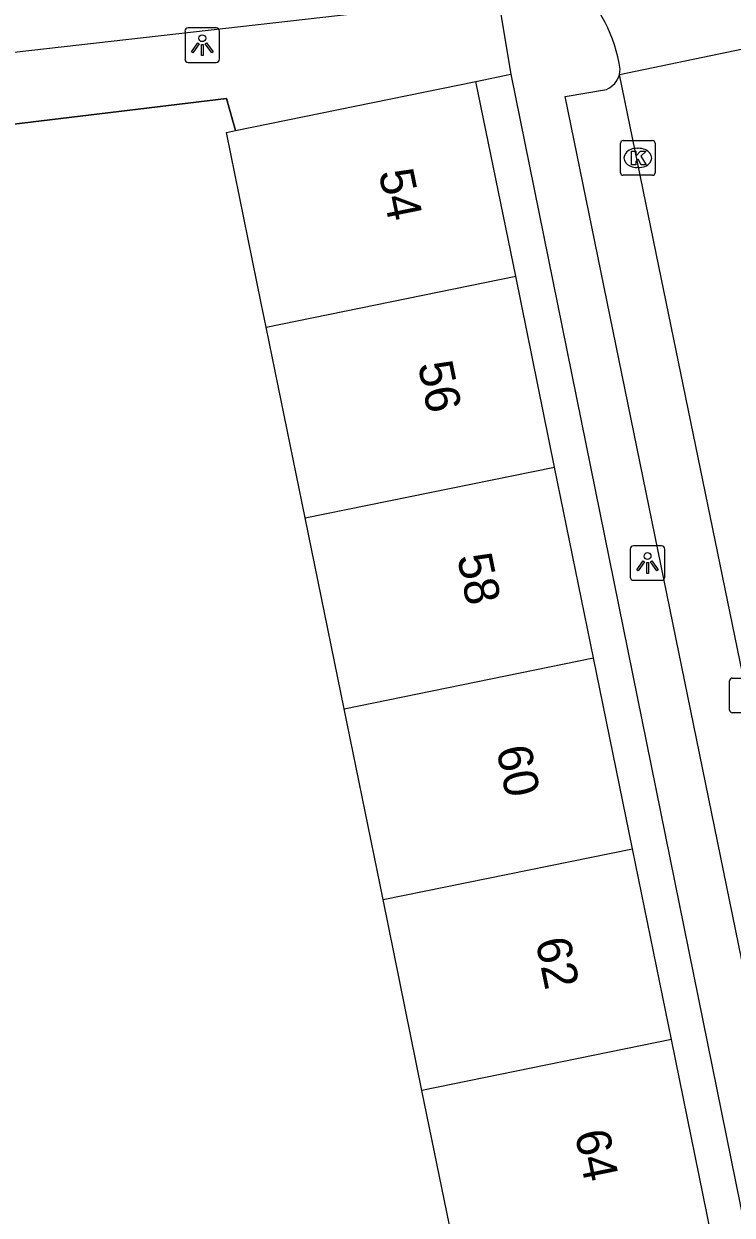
# Model space of a CAD drawing. Extents: x 162250 to 162654, y 380744 to 381605.
# Drawn here: x 162526.36 to 162546.81, y 380863.65 to 380898.07 of the extents above; entities that cross this region are included whole.
import ezdxf

# ---------------------------------------------------------------- set-up
doc = ezdxf.new("R2010")
doc.units = 0
for name, color, linetype in [('IMGEO_Kolk', 7, 'Continuous'), ('IMGEO_Lichtpunt', 7, 'Continuous'), ('IMGEO_Muur', 7, 'Continuous'), ('IMGEO_Pand', 7, 'Continuous'), ('IMGEO_Pand_nummerreeks', 7, 'Continuous'), ('IMGEO_Rijbaan_lokaal_open', 7, 'Continuous'), ('IMGEO_Voetpad_open', 7, 'Continuous')]:
    doc.layers.add(name, color=color, linetype=linetype)

msp = doc.modelspace()

# ---------------------------------------------------------------- linework, layer by layer
at = {"layer": 'IMGEO_Kolk'}
for p, q in [((162543.585, 380893.768), (162543.585, 380894.62)), ((162543.66, 380894.694), (162544.512, 380894.694)), ((162544.073, 380894.474), (162544.098, 380894.474)), ((162544.586, 380894.62), (162544.586, 380893.768)), ((162544.096, 380893.914), (162544.071, 380893.914)), ((162544.512, 380893.694), (162543.66, 380893.694)), ((162546.735, 380878.238), (162546.735, 380879.09)), ((162546.81, 380879.164), (162547.662, 380879.164)), ((162547.662, 380878.164), (162546.81, 380878.164))]:
    msp.add_line(p, q, dxfattribs=at)
for points in [[(162543.585, 380893.768), (162543.585, 380894.62)], [(162543.66, 380894.694), (162544.512, 380894.694)], [(162544.586, 380894.62), (162544.586, 380893.768)], [(162543.906, 380894.394), (162544.029, 380894.394), (162544.029, 380894.243), (162544.159, 380894.394), (162544.323, 380894.394), (162544.177, 380894.243), (162544.33, 380893.994), (162544.178, 380893.994), (162544.093, 380894.158), (162544.029, 380894.091), (162544.029, 380893.994), (162543.906, 380893.994), (162543.906, 380894.394)], [(162544.512, 380893.694), (162543.66, 380893.694)], [(162546.735, 380878.238), (162546.735, 380879.09)], [(162546.81, 380879.164), (162547.662, 380879.164)], [(162547.662, 380878.164), (162546.81, 380878.164)]]:
    msp.add_lwpolyline(points, dxfattribs=at)
for centre, start, end in [((162543.662, 380894.618), 91.552, 178.448), ((162543.662, 380894.618), 91.552, 178.448), ((162544.51, 380894.618), 1.552, 88.448), ((162544.51, 380894.618), 1.552, 88.448), ((162543.662, 380893.77), 181.552, 268.448), ((162543.662, 380893.77), 181.552, 268.448), ((162544.51, 380893.77), 271.552, 358.448), ((162544.51, 380893.77), 271.552, 358.448), ((162546.812, 380879.088), 91.552, 178.448), ((162546.812, 380879.088), 91.552, 178.448), ((162546.812, 380878.24), 181.552, 268.448), ((162546.812, 380878.24), 181.552, 268.448)]:
    msp.add_arc(centre, 0.0765, start, end, dxfattribs=at)
for centre, major_axis, ratio, start_param, end_param in [((162544.072, 380894.194), (-0.387, 0.002), 0.722429, 4.712389, 7.853982), ((162544.097, 380894.194), (-0.39, 0.002), 0.717154, 1.570796, 4.712389)]:
    msp.add_ellipse(centre, major_axis=major_axis, ratio=ratio, start_param=start_param, end_param=end_param, dxfattribs=at)
at = {"layer": 'IMGEO_Lichtpunt'}
for p, q in [((162531.01, 380897.856), (162531.01, 380897.049)), ((162531.01, 380897.856), (162531.01, 380897.049)), ((162531.912, 380897.951), (162531.104, 380897.951)), ((162531.912, 380897.951), (162531.104, 380897.951)), ((162532.006, 380897.049), (162532.006, 380897.856)), ((162532.006, 380897.049), (162532.006, 380897.856)), ((162531.104, 380896.955), (162531.912, 380896.955)), ((162531.104, 380896.955), (162531.912, 380896.955)), ((162543.867, 380882.892), (162543.867, 380882.085)), ((162543.867, 380882.892), (162543.867, 380882.085)), ((162544.769, 380882.987), (162543.961, 380882.987)), ((162544.769, 380882.987), (162543.961, 380882.987)), ((162544.863, 380882.085), (162544.863, 380882.892)), ((162544.863, 380882.085), (162544.863, 380882.892)), ((162543.961, 380881.991), (162544.769, 380881.991)), ((162543.961, 380881.991), (162544.769, 380881.991))]:
    msp.add_line(p, q, dxfattribs=at)
for points in [[(162531.384, 380897.52), (162531.423, 380897.492), (162531.235, 380897.23), (162531.197, 380897.257), (162531.384, 380897.52)], [(162531.596, 380897.492), (162531.634, 380897.519), (162531.821, 380897.257), (162531.782, 380897.229), (162531.596, 380897.492)], [(162531.486, 380897.472), (162531.533, 380897.472), (162531.533, 380897.15), (162531.486, 380897.15), (162531.486, 380897.472)], [(162544.241, 380882.556), (162544.28, 380882.528), (162544.092, 380882.266), (162544.054, 380882.293), (162544.241, 380882.556)], [(162544.343, 380882.508), (162544.39, 380882.508), (162544.39, 380882.186), (162544.343, 380882.186), (162544.343, 380882.508)], [(162544.453, 380882.528), (162544.491, 380882.555), (162544.678, 380882.293), (162544.639, 380882.265), (162544.453, 380882.528)]]:
    msp.add_lwpolyline(points, dxfattribs=at)
for centre in [(162531.509, 380897.654), (162544.366, 380882.69)]:
    msp.add_circle(centre, 0.0994, dxfattribs=at)
for centre, start, end in [((162531.104, 380897.856), 90, 180), ((162531.104, 380897.856), 90, 180), ((162531.912, 380897.856), 0, 90), ((162531.912, 380897.856), 0, 90), ((162531.104, 380897.049), 180, 270), ((162531.104, 380897.049), 180, 270), ((162531.912, 380897.049), 270, 0), ((162531.912, 380897.049), 270, 360), ((162543.961, 380882.892), 90, 180), ((162543.961, 380882.892), 90, 180), ((162544.769, 380882.892), 0, 90), ((162544.769, 380882.892), 0, 90), ((162543.961, 380882.085), 180, 270), ((162543.961, 380882.085), 180, 270), ((162544.769, 380882.085), 270, 0), ((162544.769, 380882.085), 270, 360)]:
    msp.add_arc(centre, 0.0946, start, end, dxfattribs=at)
at = {"layer": 'IMGEO_Muur'}
msp.add_lwpolyline([(162520.08, 380894.444), (162532.211, 380895.911), (162532.466, 380894.986)], dxfattribs=at)
at = {"layer": 'IMGEO_Pand'}
for points in [[(162532.466, 380894.986), (162539.411, 380896.403)], [(162540.559, 380890.774), (162539.411, 380896.403)], [(162533.354, 380889.304), (162533.212, 380890.001), (162532.206, 380894.933), (162532.466, 380894.986)], [(162533.354, 380889.304), (162540.559, 380890.774)], [(162541.684, 380885.261), (162540.559, 380890.774)], [(162534.479, 380883.791), (162533.354, 380889.304)], [(162534.479, 380883.791), (162541.684, 380885.261)], [(162542.808, 380879.748), (162541.684, 380885.261)], [(162535.604, 380878.278), (162534.479, 380883.791)], [(162535.604, 380878.278), (162542.808, 380879.748)], [(162543.933, 380874.235), (162542.808, 380879.748)], [(162536.728, 380872.765), (162535.604, 380878.278)], [(162536.728, 380872.765), (162543.933, 380874.235)], [(162545.057, 380868.723), (162543.933, 380874.235)], [(162537.853, 380867.252), (162536.728, 380872.765)], [(162545.057, 380868.723), (162537.853, 380867.252)], [(162546.206, 380863.09), (162545.057, 380868.723)], [(162539.001, 380861.626), (162537.853, 380867.252)]]:
    msp.add_lwpolyline(points, dxfattribs=at)
at = {"layer": 'IMGEO_Rijbaan_lokaal_open'}
for points in [[(162543.555, 380896.61), (162547.86, 380897.498)], [(162543.555, 380896.61), (162543.574, 380896.756)], [(162550.19, 380863.858), (162547.173, 380878.977), (162544.69, 380891.069), (162543.555, 380896.61)]]:
    msp.add_lwpolyline(points, dxfattribs=at)
msp.add_arc((162539.411, 380896.174), 4.203, 7.9562, 84.7595, dxfattribs=at)
at = {"layer": 'IMGEO_Voetpad_open'}
for points in [[(162537.937, 380900.357), (162537.657, 380900.009), (162537.79, 380898.573), (162519.955, 380896.549), (162519.833, 380897.654)], [(162539.795, 380900.36), (162540.416, 380896.616)], [(162539.411, 380896.403), (162540.416, 380896.616)], [(162540.416, 380896.616), (162547.18, 380863.294), (162546.206, 380863.09)], [(162549.753, 380864.081), (162548.554, 380863.86), (162541.985, 380895.971), (162543.178, 380896.176)], [(162532.466, 380894.986), (162532.211, 380895.911), (162520.08, 380894.444)]]:
    msp.add_lwpolyline(points, dxfattribs=at)
msp.add_arc((162542.942, 380896.762), 0.632, 291.9686, 346.0721, dxfattribs=at)

# ---------------------------------------------------------------- texts
at = {"layer": 'IMGEO_Pand_nummerreeks'}
for s, p in [('54', (162536.599, 380893.781)), ('56', (162537.731, 380888.229)), ('58', (162538.864, 380882.674)), ('60', (162539.996, 380877.122)), ('62', (162541.128, 380871.576)), ('64', (162542.261, 380866.02))]:
    msp.add_text(s, height=1, rotation=281.5287, dxfattribs=at).set_placement(p)

doc.saveas('drawing.dxf')
